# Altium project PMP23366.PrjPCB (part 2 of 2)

## Sheet PMP23366_RevB_SH3.SchDoc: Power Monitor and Source Selection
size 431 x 279 mm; Date: Not shown in title block; ApprovedBy: Not shown in title block; CheckedBy: Not shown in title block; Author: Not shown in title block; CompanyName: Not shown in title block; DrawnBy: D Strasser; Engineer: Not shown in title block; Organization: Not shown in title block; Address1: Not shown in title block; Address2: Not shown in title block; Address3: Not shown in title block; Address4: Not shown in title block; DocumentNumber: 3; Revision: Use project parameter SCH_Rev; SheetNumber: 3; SheetTotal: 4; PageSetup: Record=PageOptions¦CenterHorizontal=True¦CenterVertical=True¦PrintScale=1.00¦XCorrection=1.00¦YCorrection=1.00¦PrintKind=0¦BorderSize=5000000¦LeftOffset=0¦BottomOffset=0¦Orientation=2¦PaperLength=1000¦PaperWidth=1000¦Scale=100¦PaperSource=15¦PrintQuality=600¦MediaType=1¦DitherType=10¦PaperKind=Letter¦PrintScaleMode=1
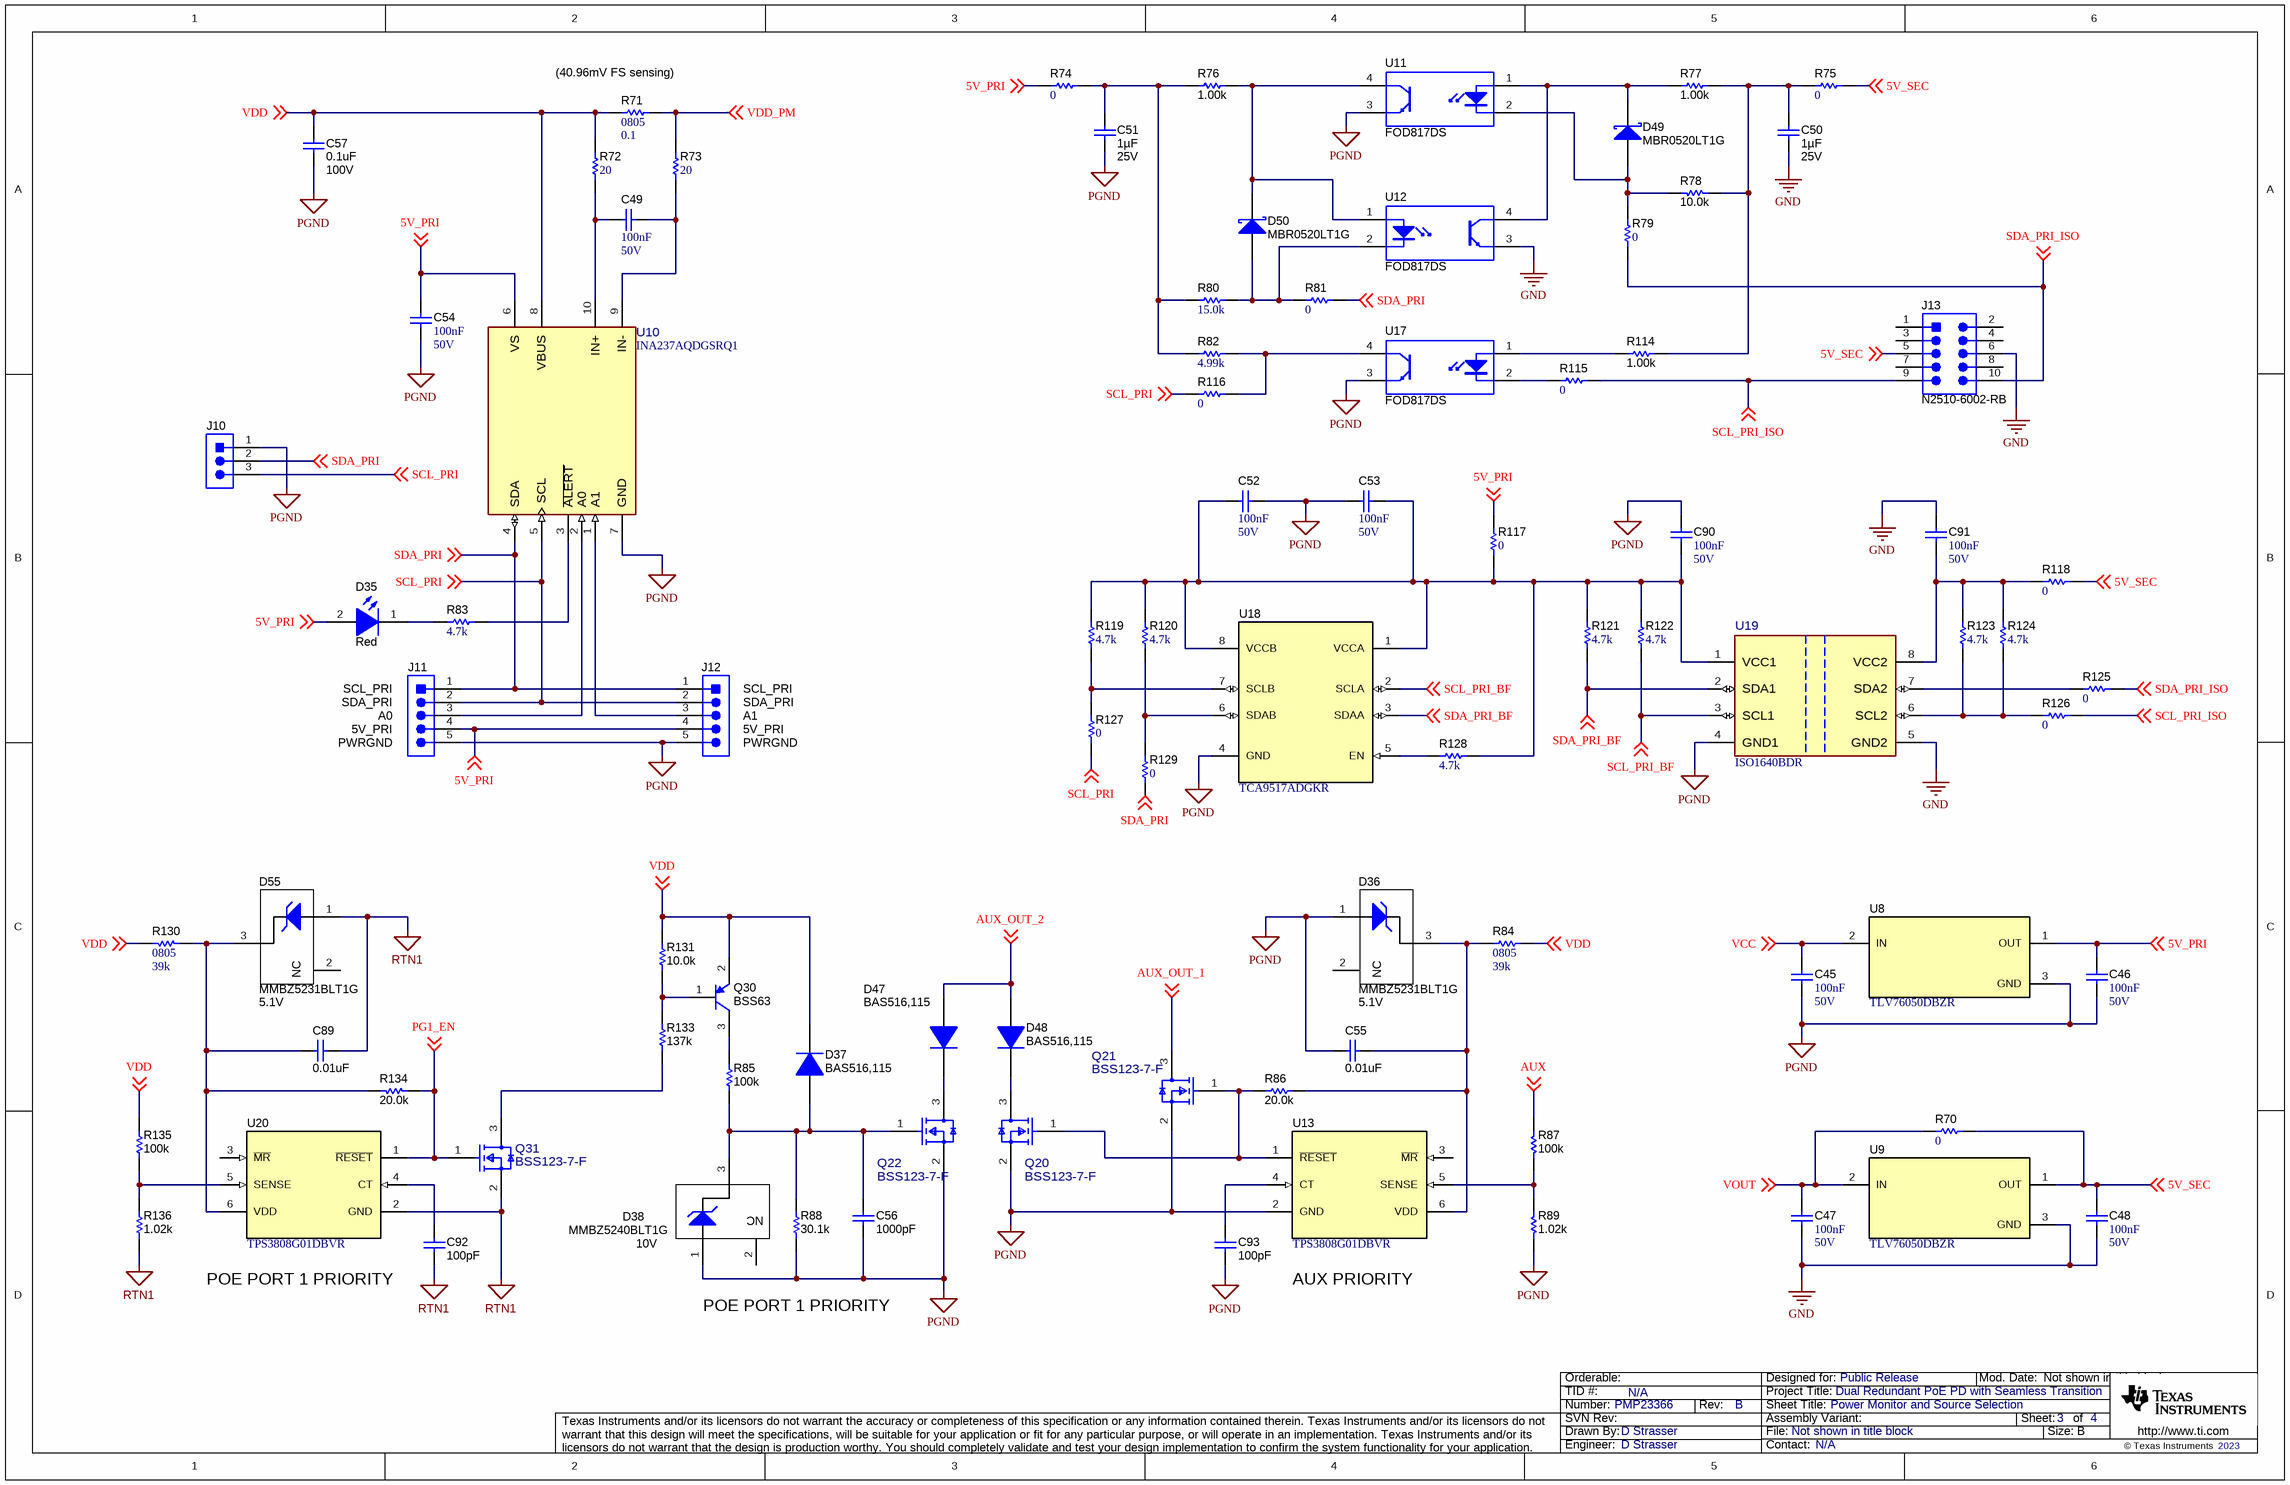
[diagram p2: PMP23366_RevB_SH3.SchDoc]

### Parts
C45  Cap_F: 100nF  VDC_V: 50V  [0603L]  (hidden comment: 885012206095)
C46  Cap_F: 100nF  VDC_V: 50V  [0603L]  (hidden comment: 885012206095)
C47  Cap_F: 100nF  VDC_V: 50V  [0603L]  (hidden comment: 885012206095)
C48  Cap_F: 100nF  VDC_V: 50V  [0603L]  (hidden comment: 885012206095)
C49  Cap_F: 100nF  VDC_V: 50V  [0603L]  (hidden comment: 885012206095)
C50  Cap_F: 1µF  VDC_V: 25V  [0805_HV1]  (hidden comment: TMK212B7105KG-T)
C51  Cap_F: 1µF  VDC_V: 25V  [0805_HV1]  (hidden comment: TMK212B7105KG-T)
C52  Cap_F: 100nF  VDC_V: 50V  [0603L]  (hidden comment: 885012206095)
C53  Cap_F: 100nF  VDC_V: 50V  [0603L]  (hidden comment: 885012206095)
C54  Cap_F: 100nF  VDC_V: 50V  [0603L]  (hidden comment: 885012206095)
C55  ValueDisplayed: 0.01uF  [0603L]  (hidden comment: Capacitor)
C56  ValueDisplayed: 1000pF  [0603L]  (hidden comment: Capacitor)
C57  ValueDisplayed: 0.1uF  Value2: 100V  [0805_HV]  (hidden comment: Capacitor)
C89  ValueDisplayed: 0.01uF  [0603L]  (hidden comment: Capacitor)
C90  Cap_F: 100nF  VDC_V: 50V  [0603L]  (hidden comment: 885012206095)
C91  Cap_F: 100nF  VDC_V: 50V  [0603L]  (hidden comment: 885012206095)
C92  ValueDisplayed: 100pF  [0603L]  (hidden comment: 885012006057)
C93  ValueDisplayed: 100pF  [0603L]  (hidden comment: 885012006057)
D35  value Red  [HLMP-Q150_Red]  (hidden comment: HLMP-Q150-F0011)
D36  MMBZ5231BLT1G  value 5.1V  [SOT-23L]
D37  BAS516,115  [SOD-523]
D38  MMBZ5240BLT1G  value 10V  [SOT-23L]
D47  BAS516,115  [SOD-523]
D48  BAS516,115  [SOD-523]
D49  MBR0520LT1G  [SOD-123]
D50  MBR0520LT1G  [SOD-123]
D55  MMBZ5231BLT1G  value 5.1V  [SOT-23L]
J10  TSW-103-08-G-S  [Samtec_TSW-103-08-x-S]  (value not drawn)
J11  HTSW-105-07-G-S  [Samtec_HTSW-105-07-G-S]  (value not drawn)
J12  HTSW-105-07-G-S  [Samtec_HTSW-105-07-G-S]  (value not drawn)
J13  N2510-6002-RB  [CONN_2510-6002]
Q20  BSS123-7-F  [FP-BSS123-7-F_SOT23-MFG]
Q21  BSS123-7-F  [FP-BSS123-7-F_SOT23-MFG]
Q22  BSS123-7-F  [FP-BSS123-7-F_SOT23-MFG]
Q30  BSS63  [SOT-23L]
Q31  BSS123-7-F  [FP-BSS123-7-F_SOT23-MFG]
R70  ValueDisplayed: 0  [0603L]  (hidden comment: CRCW06030000Z0EA)
R71  PackageReference: 0805  ValueDisplayed: 0.1  [0805_HV1]  (hidden comment: RL0805FR-070R025L)
R72  ValueDisplayed: 20  [0603L]  (hidden comment: CRCW060320R0JNEA)
R73  ValueDisplayed: 20  [0603L]  (hidden comment: CRCW060320R0JNEA)
R74  ValueDisplayed: 0  [0603L]  (hidden comment: CRCW06030000Z0EA)
R75  ValueDisplayed: 0  [0603L]  (hidden comment: CRCW06030000Z0EA)
R76  value 1.00k  [0603L]  (hidden comment: Resistor)
R77  value 1.00k  [0603L]  (hidden comment: Resistor)
R78  ValueDisplayed: 10.0k  [0603L]  (hidden comment: Resistor)
R79  ValueDisplayed: 0  [0603L]  (hidden comment: CRCW06030000Z0EA)
R80  ValueDisplayed: 15.0k  [0603L]  (hidden comment: CRCW060315K0FKEA)
R81  ValueDisplayed: 0  [0603L]  (hidden comment: CRCW06030000Z0EA)
R82  ValueDisplayed: 4.99k  [0603L]  (hidden comment: CRCW06034K99FKEA)
R83  ValueDisplayed: 4.7k  [0603L]  (hidden comment: CRCW06034K70JNEA)
R84  PackageReference: 0805  ValueDisplayed: 39k  [0805_HV1]  (hidden comment: CRCW080539K0JNEA)
R85  ValueDisplayed: 100k  [0603L]  (hidden comment: Resistor)
R86  ValueDisplayed: 20.0k  [0603L]  (hidden comment: Resistor)
R87  ValueDisplayed: 100k  [0603L]  (hidden comment: Resistor)
R88  ValueDisplayed: 30.1k  [0603L]  (hidden comment: Resistor)
R89  ValueDisplayed: 1.02k  [0603L]  (hidden comment: Resistor)
R114  value 1.00k  [0603L]  (hidden comment: Resistor)
R115  ValueDisplayed: 0  [0603L]  (hidden comment: CRCW06030000Z0EA)
R116  ValueDisplayed: 0  [0603L]  (hidden comment: CRCW06030000Z0EA)
R117  ValueDisplayed: 0  [0603L]  (hidden comment: CRCW06030000Z0EA)
R118  ValueDisplayed: 0  [0603L]  (hidden comment: CRCW06030000Z0EA)
R119  ValueDisplayed: 4.7k  [0603L]  (hidden comment: CRCW06034K70JNEA)
R120  ValueDisplayed: 4.7k  [0603L]  (hidden comment: CRCW06034K70JNEA)
R121  ValueDisplayed: 4.7k  [0603L]  (hidden comment: CRCW06034K70JNEA)
R122  ValueDisplayed: 4.7k  [0603L]  (hidden comment: CRCW06034K70JNEA)
R123  ValueDisplayed: 4.7k  [0603L]  (hidden comment: CRCW06034K70JNEA)
R124  ValueDisplayed: 4.7k  [0603L]  (hidden comment: CRCW06034K70JNEA)
R125  ValueDisplayed: 0  [0603L]  (hidden comment: CRCW06030000Z0EA)
R126  ValueDisplayed: 0  [0603L]  (hidden comment: CRCW06030000Z0EA)
R127  ValueDisplayed: 0  [0603L]  (hidden comment: CRCW06030000Z0EA)
R128  ValueDisplayed: 4.7k  [0603L]  (hidden comment: CRCW06034K70JNEA)
R129  ValueDisplayed: 0  [0603L]  (hidden comment: CRCW06030000Z0EA)
R130  PackageReference: 0805  ValueDisplayed: 39k  [0805_HV1]  (hidden comment: CRCW080539K0JNEA)
R131  ValueDisplayed: 10.0k  [0603L]  (hidden comment: Resistor)
R133  ValueDisplayed: 137k  [0603L]  (hidden comment: Resistor)
R134  ValueDisplayed: 20.0k  [0603L]  (hidden comment: Resistor)
R135  ValueDisplayed: 100k  [0603L]  (hidden comment: Resistor)
R136  ValueDisplayed: 1.02k  [0603L]  (hidden comment: Resistor)
U8  TLV76050DBZR  [DBZ0003A_N]
U9  TLV76050DBZR  [DBZ0003A_N]
U10  INA237AQDGSRQ1  [DGS0010A-MFG]
U11  FOD817DS  [N04C]
U12  FOD817DS  [N04C]
U13  TPS3808G01DBVR  [DBV0006A_N]
U17  FOD817DS  [N04C]
U18  TCA9517ADGKR  [DGK0008A_N]
U19  ISO1640BDR  [D0008A-MFG]
U20  TPS3808G01DBVR  [DBV0006A_N]

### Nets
GND: C47.2 C48.2 C50.1 C91.1 J13.6 U9.3(GND) U12.3(E) U19.5(GND2)
PGND: C45.2 C46.2 C51.1 C52.1 C53.2 C54.2 C55.1 C56.2 C57.1 C90.1 C93.2 D36.1(A) D38.1(A) J10.1 J11.5 J12.5 Q20.2(S) Q21.2(S) Q22.2(S) R88.1 R89.1 U8.3(GND) U10.7(GND) U11.3(E) U13.2(GND) U17.3(E) U18.4(GND) U19.4(GND1)
RTN1: C89.1 C92.2 D55.1(A) Q31.2(S) R136.1 U20.2(GND)
5V_PRI: C46.1 C54.1 D35.2(A) J11.4 J12.4 R74.1 R117.2 U8.1(OUT) U10.6(VS) ; off-sheet 5V_PRI
5V_SEC: C48.1 J13.5 R70.2 R75.1 R118.2 U9.1(OUT) ; off-sheet 5V_SEC
AUX: R87.2 ; off-sheet AUX
AUX_OUT_1: Q21.3(D) ; off-sheet AUX_OUT_1
AUX_OUT_2: D47.2(A) D48.2(A) ; off-sheet AUX_OUT_2
PG1_EN: Q31.1(G) R134.2 U20.1(~{RESET}) ; off-sheet PG1_EN
SCL_PRI: J10.3 J11.2 J12.2 R116.2 R127.1 U10.5(SCL) ; off-sheet SCL_PRI
SCL_PRI_BF: R122.1 U18.2(SCLA) U19.3(SCL1) ; off-sheet SCL_PRI_BF
SCL_PRI_ISO: J13.9 R115.2 R126.2 ; off-sheet SCL_PRI_ISO
SDA_PRI: J10.2 J11.1 J12.1 R81.2 R129.1 U10.4(SDA) ; off-sheet SDA_PRI
SDA_PRI_BF: R121.1 U18.3(SDAA) U19.2(SDA1) ; off-sheet SDA_PRI_BF
SDA_PRI_ISO: J13.10 R79.2 R125.2 ; off-sheet SDA_PRI_ISO
VCC: C45.1 U8.2(IN) ; off-sheet VCC
VDD: C57.2 D37.1(K) Q30.2(E) R71.1 R72.1 R84.1 R130.1 R131.2 R135.2 U10.8(VBUS) ; off-sheet VDD
VDD_PM: R71.2 R73.1 ; off-sheet VDD_PM
VOUT: C47.1 R70.1 U9.2(IN) ; off-sheet VOUT
NetC49_1: C49.1 R73.2 U10.9(IN-)
NetC49_2: C49.2 R72.2 U10.10(IN+)
NetC50_2: C50.2 R75.2 R77.2 R78.2 R114.2
NetC51_2: C51.2 R74.2 R76.1 R80.1 R82.1
NetC52_2: C52.2 C53.1 C90.2 R117.1 R119.1 R120.2 R121.2 R122.2 R128.1 U18.1(VCCA) U18.8(VCCB) U19.1(VCC1)
NetC55_2: C55.2 D36.3(K) R84.2 R86.1 U13.6(VDD)
NetC56_1: C56.1 D37.2(A) D38.3(K) Q22.1(G) R85.1 R88.2
NetC89_2: C89.2 D55.3(K) R130.2 R134.1 U20.6(VDD)
NetC91_2: C91.2 R118.1 R123.2 R124.2 U19.8(VCC2)
NetC92_1: C92.1 U20.4(CT)
NetC93_1: C93.1 U13.4(CT)
NetD35_1: D35.1(K) R83.1
NetD47_1: D47.1(K) Q22.3(D)
NetD48_1: D48.1(K) Q20.3(D)
NetD49_1: D49.1(K) R77.1 U11.1(A) U12.4(C)
NetD49_2: D49.2(A) R78.1 R79.1 U11.2(K)
NetD50_1: D50.1(K) R76.2 U11.4(C) U12.1(A)
NetD50_2: D50.2(A) R80.2 R81.1 U12.2(K)
NetJ11_3: J11.3 U10.2(A0)
NetJ12_3: J12.3 U10.1(A1)
NetQ20_1: Q20.1(G) Q21.1(G) R86.2 U13.1(~{RESET})
NetQ30_1: Q30.1(B) R131.1 R133.1
NetQ30_3: Q30.3(C) R85.2
NetQ31_3: Q31.3(D) R133.2
NetR82_2: R82.2 R116.1 U17.4(C)
NetR83_2: R83.2 U10.3(~{ALERT})
NetR87_1: R87.1 R89.2 U13.5(SENSE)
NetR114_1: R114.1 U17.1(A)
NetR115_1: R115.1 U17.2(K)
NetR119_2: R119.2 R127.2 U18.7(SCLB)
NetR120_1: R120.1 R129.2 U18.6(SDAB)
NetR123_1: R123.1 R124.1 R126.1 U19.6(SCL2)
NetR125_1: R125.1 U19.7(SDA2)
NetR128_2: R128.2 U18.5(EN)
NetR135_1: R135.1 R136.2 U20.5(SENSE)

Not connected (* = marked no-connect by the designer): D36 2(NC); D38 2(NC); D55 2(NC); J13 1 2 3 4 7 8; U13 3(~{MR}); U20 3(~{MR})

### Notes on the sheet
- (near R71) (40.96mV FS sensing)
- (near J11) SDA_PRI
- SCL_PRI
- (near J12) SCL_PRI
- (near J12) SDA_PRI
- (near J11) A0
- (near J11) 5V_PRI
- (near J11) PWRGND
- (near J12) A1
- (near J12) 5V_PRI
- (near J12) PWRGND
- POE PORT 1 PRIORITY
- AUX PRIORITY

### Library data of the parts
C45-C49 C52-C54 C90 C91 = CMP-0006837-4: CAP, CERM, 0.1 uF, 50 V, +/- 10%, X7R, 0603; Manufacturer: Wurth Elektronik; TaMin_C: -55°C; Polarized: N; SizeAreaWB_mm2: 4.68; Value1: Unknown; U/M: EA; Value: 0.1uF; TaMax_C: 125°C; SizeZ_mm: 1; SizeX_mm: 1.6; SizeY_mm: 0.8; Cap_Case: 0603; SizeArea_mm2: 1.28; AEC Category: Q200
C50 C51 = CMP-0008412-2: CAP, CERM, 1 uF, 25 V, +/- 10%, X7R, 0805; Manufacturer: Taiyo Yuden; TaMin_C: -55°C; Polarized: N; SizeAreaWB_mm2: 6.75; Value1: Unknown; U/M: EA; Value: 1uF; TaMax_C: 125°C; SizeZ_mm: 1.45; SizeX_mm: 2; SizeY_mm: 1.25; Cap_Case: 0805; SizeArea_mm2: 2.5; AEC Category: Q200
C55 C89 = CMP-0007043-4: CAP, CERM, 0.01 uF, 50 V, +/- 10%, X7R, 0603; PartNumber: C1608X7R1H103K080AA; Manufacturer: TDK; Polarized: N; Value: 0.01uF; U/M: EA; Cap_F: 10nF; ESR_ohm: 0.0539; Value1: 0.0539 ohm; VDC_V: 50V; TaMin_C: -55°C; TaMax_C: 125°C; Cap_Case: 0603; SizeArea_mm2: 1.28; SizeAreaWB_mm2: 4.68; SizeX_mm: 1.6; SizeY_mm: 0.8; SizeZ_mm: 1; AEC Category: Q200
C56 = CMP-0007432-5: CAP, CERM, 1000 pF, 50 V, +/- 10%, X7R, 0603; PartNumber: GRM188R71H102KA01D; Manufacturer: MuRata; Polarized: N; Value: 1000pF; U/M: EA; Cap_F: 1nF; Value1: Unknown; VDC_V: 50V; TaMin_C: -55°C; TaMax_C: 125°C; Cap_Case: 0603; SizeArea_mm2: 1.28; SizeAreaWB_mm2: 4.68; SizeX_mm: 1.6; SizeY_mm: 0.8; SizeZ_mm: 1; AEC Category: Q200
C57 = CMP-0007886-2: CAP, CERM, 0.1 uF, 100 V, +/- 10%, X7R, 0805; PartNumber: C2012X7R2A104K125AA; Manufacturer: TDK; Polarized: N; Value: 0.1uF; U/M: EA; Cap_F: 100nF; ESR_ohm: 0.020726; Value1: 0.020726 ohm; IRMS_A: 1.456A; TaMin_C: -55°C; TaMax_C: 125°C; Cap_Case: 0805; SizeArea_mm2: 2.5; SizeAreaWB_mm2: 6.75; SizeX_mm: 2; SizeY_mm: 1.25; SizeZ_mm: 1.45; AEC Category: Q200
C92 C93 = CMP-0006822-4: CAP, CERM, 100 pF, 50 V, +/- 5%, C0G/NP0, 0603; Manufacturer: Wurth Elektronik; TaMin_C: -55°C; Polarized: N; SizeAreaWB_mm2: 4.68; Value1: Unknown; U/M: EA; Value: 100pF; TaMax_C: 125°C; SizeZ_mm: 1; SizeX_mm: 1.6; SizeY_mm: 0.8; Cap_Case: 0603; Value2: 50V; SizeArea_mm2: 1.28; AEC Category: Q200
D35 = CMP-0002939-3: LED, Red, SMD; Manufacturer: Avago; Vf_V: 1.6V; Ir_A: 10µA; Value1: W; Vr_V: 15V; Io_A: 1mA; Angle: 90; Tjmax_C: 100°C
D36 D55 = CMP-0005999-3: Diode, Zener, 5.1 V, 225 mW, SOT-23; Manufacturer: ON Semiconductor; SizeZ_mm: 1.1; SizeAreaWB_mm2: 14; Power_W: 225mW; SizeY_mm: 3; SizeArea_mm2: 7.5; RJA_CperW: 556; SizeX_mm: 2.5; AEC Category: Q101; Value1: 0.225W
D37 D47 D48 = CMP-0076979-3: Diode, Switching, 100 V, 0.25 A, SOD-523; Manufacturer: Nexperia; Value: 100V; SizeAreaWB_mm2: 5.13; Vf_V: 1.25V; SizeArea_mm2: 1.53; SizeY_mm: 0.9; Green_Lifecycle: Not Set; AEC Category: Q101; SizeX_mm: 1.7; Green_REACh: Incomplete; Io_A: 250mA; TJmax_C: 150°C; SizeZ_mm: 0.65; Value1: 0.25A
D38 = CMP-0005949-3: Diode, Zener, 10 V, 225 mW, SOT-23; Manufacturer: ON Semiconductor; SizeAreaWB_mm2: 14; RJA_CperW: 556; SizeArea_mm2: 7.5; SizeY_mm: 3; Value1: 0.225W; SizeZ_mm: 1.1; AEC Category: Q101; SizeX_mm: 2.5; Power_W: 225mW
D49 D50 = CMP-0028524-2: Diode, Schottky, 20 V, 0.5 A, SOD-123; Manufacturer: ON Semiconductor; Green_REACh: Passed; TJmax_C: 125°C; Value1: 0.5A; SizeZ_mm: 1.35; Value2: 0.385V; Vf_V: 385mV; AEC Category: Q101; SizeY_mm: 1.7; Value: 20V; Io_A: 500mA; SizeX_mm: 3.85; Green_Lifecycle: Active; RJC_CperW: 150; SizeAreaWB_mm2: 13.095; SizeArea_mm2: 6.545
J10 = CMP-0079327-1: Header, 2.54mm, 3x1, Gold, TH; Manufacturer: Samtec; Pitch_mm: 2.54; Gender: Male; Cert_UL: Y; Shrouded: N; Row_Count: 1
J11 J12 = CMP-0075485-1: Header, 100mil, 5x1, Gold, TH; Manufacturer: Samtec; Green_REACh: Passed; CT: False; Green_Lifecycle: Active; CNHeader: True
J13 = CMP-0055448-2: Header (shrouded), 100mil, 5x2, High-Temperature, Gold, TH; Manufacturer: 3M; Green_Lifecycle: Active; Green_REACh: Passed
Q20-Q22 Q31 = CMP-0087176-1: MOSFET N-CH 100V 170MA SOT23-3; Manufacturer: Diodes Incorporated; Vgs_V: 20V; ChMode: False; AEC Qualified: No; SizeZ_mm: 1.1mm; Rdson45_ohm: 6
Q30 = CMP-0000366-2: Transistor, PNP, 100 V, 0.2 A, SOT-23; Manufacturer: Fairchild Semiconductor; TaMax_C: 150°C; Value1: 0.2 A; Vcesat1_V: 250mV; SizeX_mm: 2.5; SizeY_mm: 3; TaMin_C: -55°C; IcRated_A: 200mA; CompType: BJT; SizeZ_mm: 1.1; AEC Qualified: N; Value: 100 V; SizeArea_mm2: 7.5; NPN: 0; Vceo_V: 100V; PNP: 1; AEC Category: Q101; SizeAreaWB_mm2: 14; U/M: EA
R70 R74 R75 R79 R81 R115-R118 R125-R127 R129 = CMP-0025697-4: RES, 0, 5%, 0.1 W, AEC-Q200 Grade 0, 0603; Manufacturer: Vishay-Dale; Power_W: 100mW; TempCo: 200 ppm/C; Value_Code: 0000; Value: 0; EIA_Code: E24; SizeX_mm: 1.6; SizeY_mm: 0.8; SizeZ_mm: 1; Value2: 0.1W; SizeArea_mm2: 1.28; AEC Qualified: Y; VDC_V: 75V; AEC Category: Q200
R71 = CMP-0080609-1: RES, 0.025, 1%, 0.125 W, AEC-Q200 Grade 1, 0805; Manufacturer: Yageo America; Power_W: 125mW; TempCo: 600 ppm/C; SizeAreaWB_mm2: 6.75; Value_Code: R100; Value: 0.1; EIA_Code: E96; Res_ohm: 0.025; SizeX_mm: 2; SizeY_mm: 1.25; SizeZ_mm: 1.45; Value2: 0.125W; SizeArea_mm2: 2.5; AEC Qualified: Y; AEC Grade: 1; AEC Category: Q200
R72 R73 = CMP-0025754-4: RES, 20, 5%, 0.1 W, AEC-Q200 Grade 0, 0603; Manufacturer: Vishay-Dale; Power_W: 100mW; TempCo: 200 ppm/C; Value_Code: 20R0; Value: 20; EIA_Code: E24; SizeX_mm: 1.6; SizeY_mm: 0.8; SizeZ_mm: 1; Value2: 0.1W; SizeArea_mm2: 1.28; AEC Qualified: Y; VDC_V: 75V; AEC Category: Q200; AEC Grade: 0
R76 R77 R114 = CMP-0022109-5: RES, 1.00 k, 1%, 0.1 W, AEC-Q200 Grade 0, 0603; PartNumber: CRCW06031K00FKEA; Manufacturer: Vishay-Dale; Res_ohm: 1k; Value_Code: 1k00; Power_W: 100mW; Value2: 0.1W; VDC_V: 75V; TempCo: 100 ppm/C; EIA_Code: E96; AEC Category: Q200; AEC Grade: 0; AEC Qualified: Y; SizeArea_mm2: 1.28; SizeX_mm: 1.6; SizeY_mm: 0.8; SizeZ_mm: 1
R78 R131 = CMP-0021998-4: RES, 10.0 k, 1%, 0.1 W, AEC-Q200 Grade 0, 0603; PartNumber: CRCW060310K0FKEA; Manufacturer: Vishay-Dale; Value: 10.0k; Res_ohm: 10k; Value_Code: 10k0; Power_W: 100mW; Value2: 0.1W; VDC_V: 75V; TempCo: 100 ppm/C; SizeArea_mm2: 1.28; SizeX_mm: 1.6; SizeY_mm: 0.8; SizeZ_mm: 1; EIA_Code: E96; AEC Category: Q200; AEC Qualified: Y; AEC Grade: 0
R80 = CMP-0022066-4: RES, 15.0 k, 1%, 0.1 W, AEC-Q200 Grade 0, 0603; Manufacturer: Vishay-Dale; Power_W: 100mW; TempCo: 100 ppm/C; Value_Code: 15k0; Value: 15.0k; EIA_Code: E96; Res_ohm: 15k; SizeX_mm: 1.6; SizeY_mm: 0.8; SizeZ_mm: 1; Value2: 0.1W; SizeArea_mm2: 1.28; AEC Qualified: Y; VDC_V: 75V; AEC Category: Q200; AEC Grade: 0
R82 = CMP-0022458-4: RES, 4.99 k, 1%, 0.1 W, AEC-Q200 Grade 0, 0603; Manufacturer: Vishay-Dale; Power_W: 100mW; TempCo: 100 ppm/C; Value_Code: 4k99; Value: 4.99k; EIA_Code: E96; SizeX_mm: 1.6; SizeY_mm: 0.8; SizeZ_mm: 1; Value2: 0.1W; SizeArea_mm2: 1.28; AEC Qualified: Y; VDC_V: 75V; AEC Category: Q200; AEC Grade: 0
R83 R119-R124 R128 = CMP-0025817-4: RES, 4.7 k, 5%, 0.1 W, AEC-Q200 Grade 0, 0603; Manufacturer: Vishay-Dale; Power_W: 100mW; TempCo: 200 ppm/C; Value_Code: 4k70; Value: 4.7k; EIA_Code: E24; SizeX_mm: 1.6; SizeY_mm: 0.8; SizeZ_mm: 1; Value2: 0.1W; SizeArea_mm2: 1.28; AEC Qualified: Y; VDC_V: 75V; AEC Category: Q200; AEC Grade: 0
R84 R130 = CMP-0020536-3: RES, 39 k, 5%, 0.125 W, AEC-Q200 Grade 0, 0805; Manufacturer: Vishay-Dale; Power_W: 125mW; TempCo: 200 ppm/C; Value_Code: 39k0; Value: 39k; EIA_Code: E24; SizeX_mm: 2; SizeY_mm: 1.25; SizeZ_mm: 1.45; Value2: 0.125W; SizeArea_mm2: 2.5; AEC Qualified: Y; VDC_V: 150V; AEC Category: Q200; AEC Grade: 0
R85 R87 R135 = CMP-0021990-4: RES, 100 k, 1%, 0.1 W, AEC-Q200 Grade 0, 0603; PartNumber: CRCW0603100KFKEA; Manufacturer: Vishay-Dale; Value: 100k; Power_W: 100mW; Value2: 0.1W; VDC_V: 75V; TempCo: 100 ppm/C; SizeArea_mm2: 1.28; SizeX_mm: 1.6; SizeY_mm: 0.8; SizeZ_mm: 1; EIA_Code: E96; AEC Category: Q200; AEC Qualified: Y; AEC Grade: 0
R86 R134 = CMP-0022204-4: RES, 20.0 k, 1%, 0.1 W, AEC-Q200 Grade 0, 0603; PartNumber: CRCW060320K0FKEA; Manufacturer: Vishay-Dale; Value: 20.0k; Res_ohm: 20k; Value_Code: 20k0; Power_W: 100mW; Value2: 0.1W; VDC_V: 75V; TempCo: 100 ppm/C; EIA_Code: E96; SizeArea_mm2: 1.28; SizeX_mm: 1.6; SizeY_mm: 0.8; SizeZ_mm: 1; AEC Category: Q200; AEC Qualified: Y; AEC Grade: 0
R88 = CMP-0022324-4: RES, 30.1 k, 1%, 0.1 W, AEC-Q200 Grade 0, 0603; PartNumber: CRCW060330K1FKEA; Manufacturer: Vishay-Dale; Value: 30.1k; Value_Code: 30k1; Power_W: 100mW; Value2: 0.1W; VDC_V: 75V; TempCo: 100 ppm/C; SizeArea_mm2: 1.28; SizeX_mm: 1.6; SizeY_mm: 0.8; SizeZ_mm: 1; EIA_Code: E96; AEC Category: Q200; AEC Qualified: Y; AEC Grade: 0
R89 R136 = CMP-0022110-4: RES, 1.02 k, 1%, 0.1 W, AEC-Q200 Grade 0, 0603; PartNumber: CRCW06031K02FKEA; Manufacturer: Vishay-Dale; Value: 1.02k; Value_Code: 1k02; Power_W: 100mW; Value2: 0.1W; VDC_V: 75V; TempCo: 100 ppm/C; SizeArea_mm2: 1.28; SizeX_mm: 1.6; SizeY_mm: 0.8; SizeZ_mm: 1; EIA_Code: E96; AEC Category: Q200; AEC Qualified: Y; AEC Grade: 0
R133 = CMP-0022040-4: RES, 137 k, 1%, 0.1 W, AEC-Q200 Grade 0, 0603; PartNumber: CRCW0603137KFKEA; Manufacturer: Vishay-Dale; Value: 137k; Power_W: 100mW; Value2: 0.1W; VDC_V: 75V; TempCo: 100 ppm/C; SizeArea_mm2: 1.28; SizeX_mm: 1.6; SizeY_mm: 0.8; SizeZ_mm: 1; EIA_Code: E96; AEC Category: Q200; AEC Qualified: Y; AEC Grade: 0
U8 U9 = CMP-0074892-1: 100-mA, 30-V, Fixed-Output, Linear-Voltage Regulator, DBZ0003A (SOT-23-3); Alternate PartNumber: TLV76050DBZT; Alternate Manufacturer: Texas Instruments; SizeAreaWB_mm2: 14.0; SizeZ_mm: 1.12; SizeX_mm: 2.5; SizeY_mm: 3.0; SizeArea_mm2: 7.5; CompType: IC; AEC Qualified: N; AEC Category: Q200
U10 = CMP-0088571-2: High-Voltage, Zero-Drift, 16-Bit ADC, I 2C, Bidirectional Shunt Current, Bus Voltage, Power, and Temperature Monitor; Manufacturer: Texas Instruments; Number Of Converters: 1; AEC Category: Q200; CompType: IC; Standoff Height: 0.05mm; Interface: I2C; Data Polarity: Differential; SizeZ_mm: 1.1mm
U11 U12 U17 = CMP-0006165-3: Optocoupler, 5 kV, 300-600% CTR, SMT; Manufacturer: Fairchild Semiconductor; CTR (Max): 600%; CTR (Min): 300%; Voltage_Isolation_Vrms: 5kV
U13 U20 = CMP-0032355-1: Low Quiescent Current, Programmable-Delay Supervisory Circuit, 1 Supply Monitored, -40 to 125 degC, 6-pin SOT-23 (DBV), Green (RoHS & no Sb/Br); Manufacturer: Texas Instruments; # of Supplies Monitored: 1; Iq(Typ)(uA): 2.4; Output Driver Type / Reset Output: Active-low, Open-drain; Rating: Catalog; SubFamily: Supervisor and Reset IC; Threshold Voltage 1 (typ)(Typ)(V): Adjustable; VCC(Max)(V): 6.5; VCC(Min)(V): 1.7
U18 = CMP-0065788-2: Level-Translating I2C Bus Repeater, DGK0008A (VSSOP-8); Alternate Manufacturer: Texas Instruments; SizeAreaWB_mm2: 23.6; SizeZ_mm: 1.1; SizeX_mm: 4.9; SizeY_mm: 3; SizeArea_mm2: 14.7; CompType: IC; AEC Category: Q200; AEC Qualified: N
U19 = CMP-0091761-1: Manufacturer: Texas Instruments; TaMin_C: -40°C; AEC Qualified: No; Standoff Height: 0.11mm; Min Supply Voltage: 2.25V; SizeZ_mm: 1.75mm; Nominal Supply Current: 2.7-5.3mA; Interface: I2C; TaMax_C: +125°C; TJmax_C: +150°C; Max Supply Voltage: 5.5V

## Sheet PMP23366_RevB_SH4.SchDoc: Active Clamp Forward Converter
size 431 x 279 mm; Date: Not shown in title block; ApprovedBy: Not shown in title block; CheckedBy: Not shown in title block; Author: Not shown in title block; CompanyName: Not shown in title block; DrawnBy: D Strasser; Engineer: Not shown in title block; Organization: Not shown in title block; Address1: Not shown in title block; Address2: Not shown in title block; Address3: Not shown in title block; Address4: Not shown in title block; DocumentNumber: 4; Revision: Use project parameter SCH_Rev; SheetNumber: 4; SheetTotal: 4; PageSetup: Record=PageOptions¦CenterHorizontal=True¦CenterVertical=True¦PrintScale=1.00¦XCorrection=1.00¦YCorrection=1.00¦PrintKind=0¦BorderSize=5000000¦LeftOffset=0¦BottomOffset=0¦Orientation=2¦PaperLength=1000¦PaperWidth=1000¦Scale=100¦PaperSource=15¦PrintQuality=600¦MediaType=1¦DitherType=10¦PaperKind=Letter¦PrintScaleMode=1
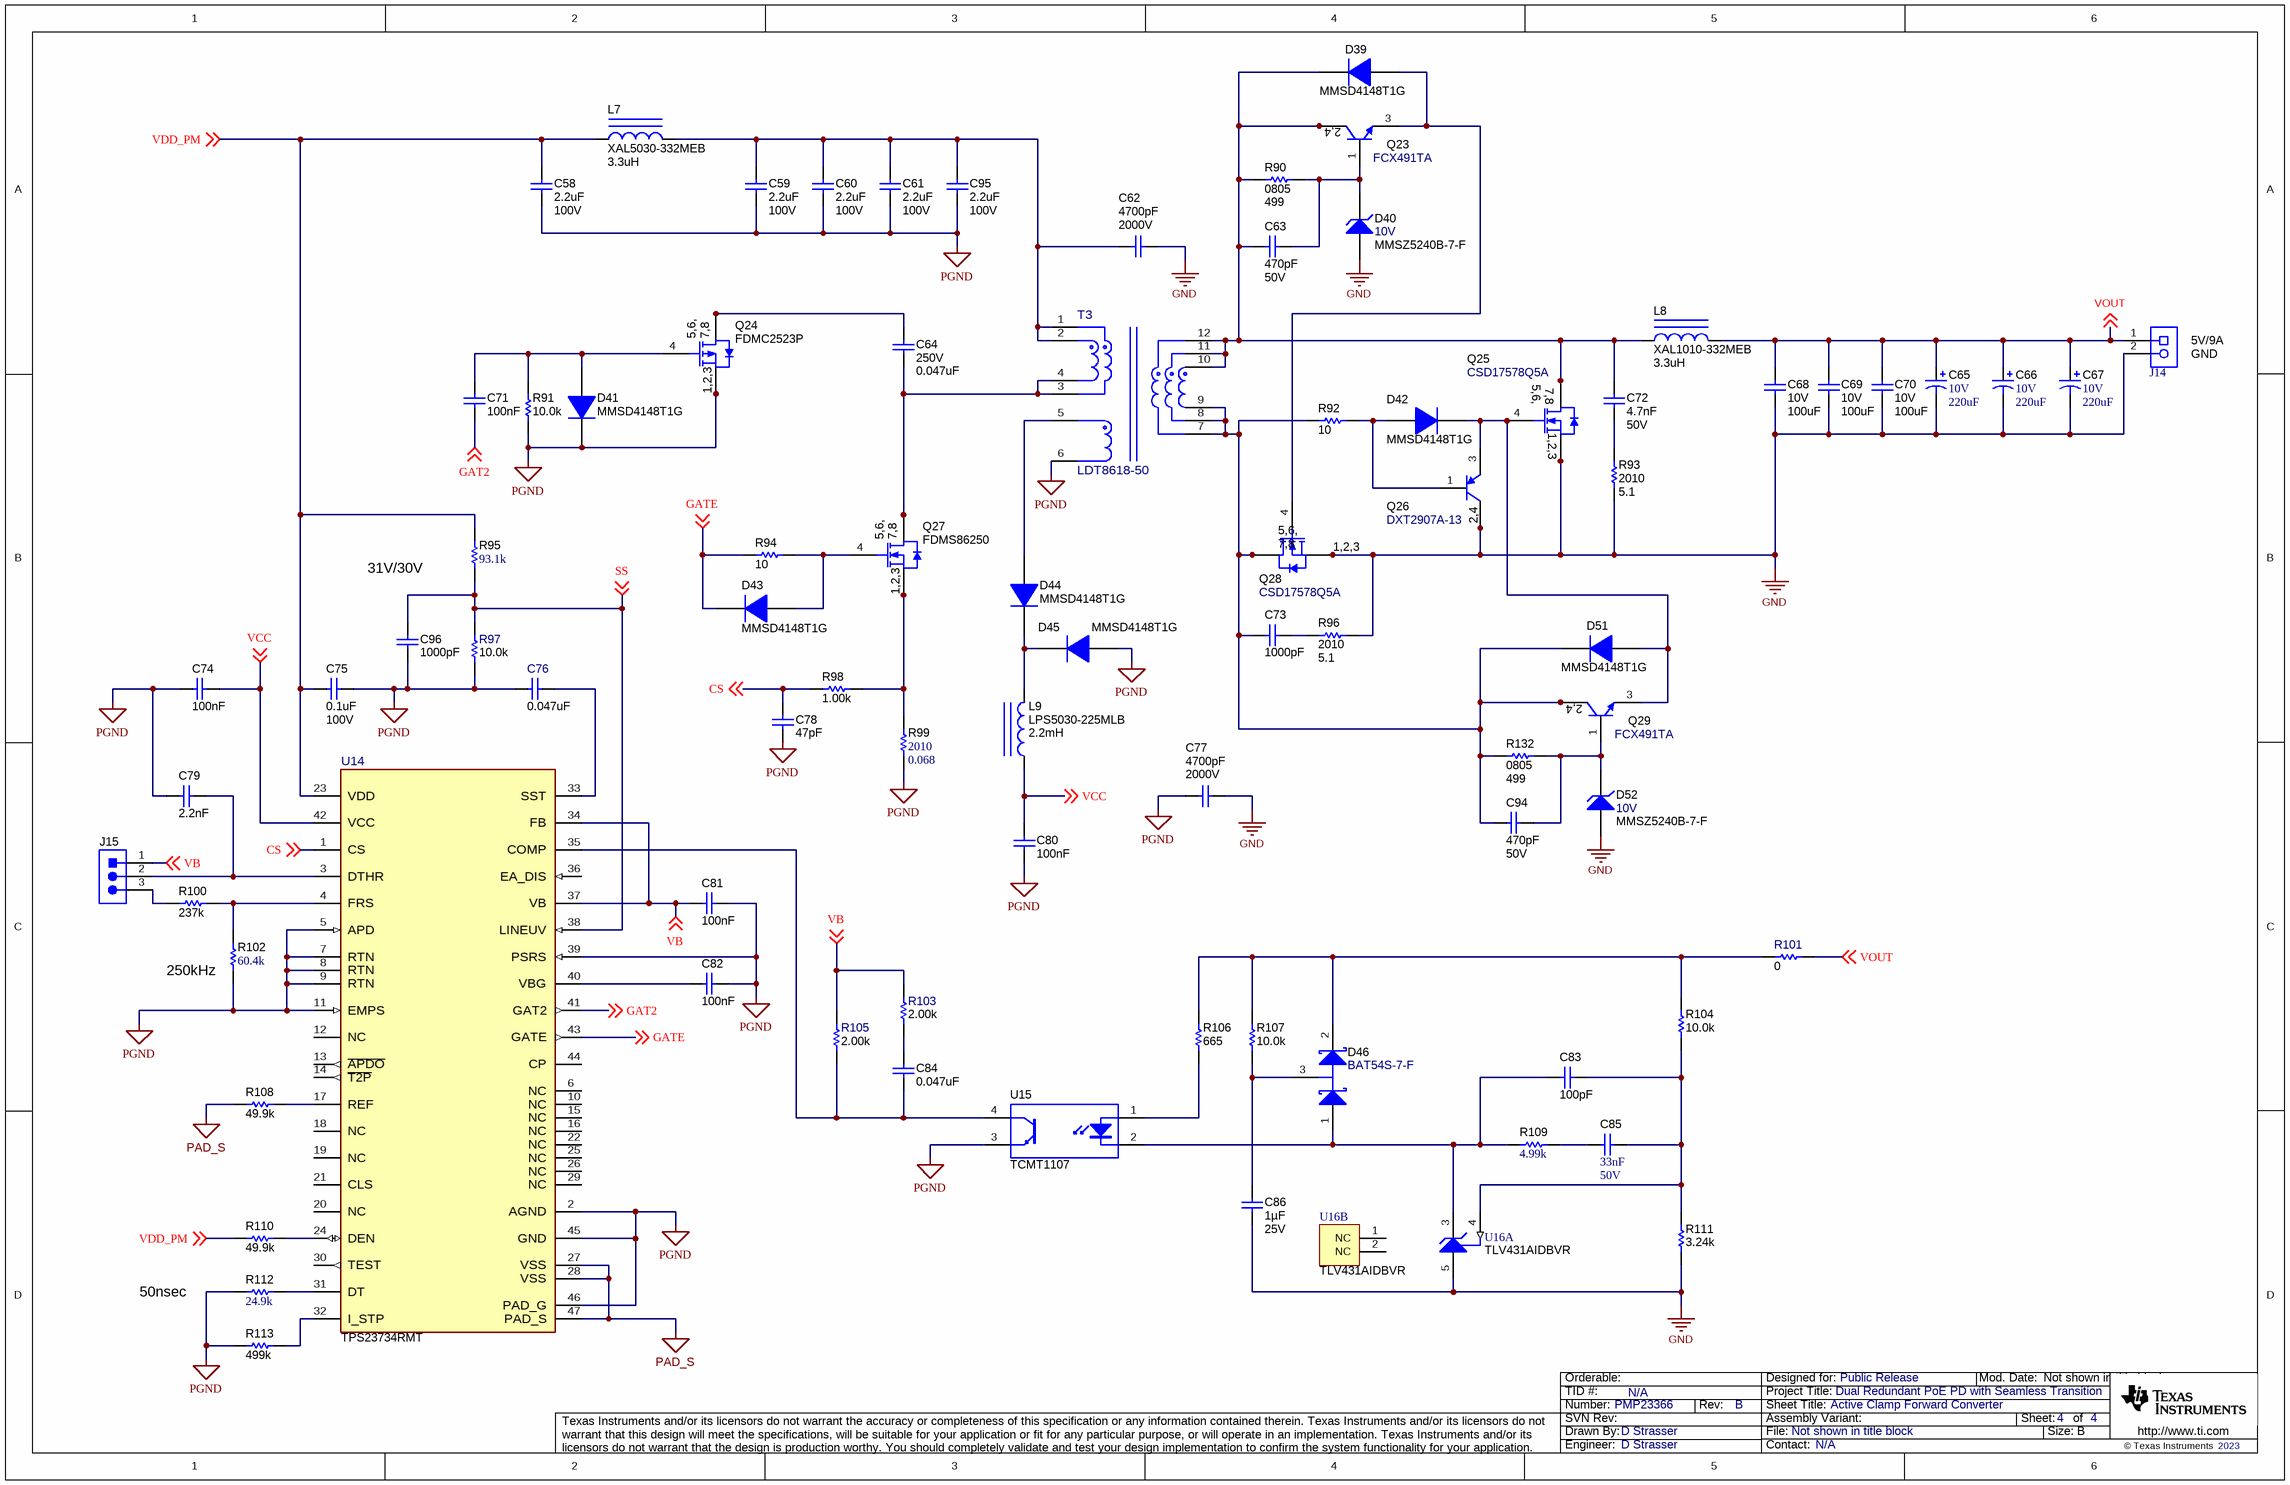
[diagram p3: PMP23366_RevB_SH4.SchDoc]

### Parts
C58  ValueDisplayed: 2.2uF  VDC_V: 100V  [1210_270]  (hidden comment: Capacitor)
C59  ValueDisplayed: 2.2uF  VDC_V: 100V  [1210_270]  (hidden comment: Capacitor)
C60  ValueDisplayed: 2.2uF  VDC_V: 100V  [1210_270]  (hidden comment: Capacitor)
C61  ValueDisplayed: 2.2uF  VDC_V: 100V  [1210_270]  (hidden comment: Capacitor)
C62  Value2: 2000V  ValueDisplayed: 4700pF  [1812_HV]  (hidden comment: Capacitor)
C63  Cap_F: 470pF  VDC_V: 50V  [0603L]  (hidden comment: 885012206081)
C64  VDC_V: 250V  ValueDisplayed: 0.047uF  [1206_180]  (hidden comment: GRM31CR72E473KW03L)
C65  VDC_V: 10V  ValueDisplayed: 220uF  [CAPSMT_62_F61]  (hidden comment: 10SVPE220M)
C66  VDC_V: 10V  ValueDisplayed: 220uF  [CAPSMT_62_F61]  (hidden comment: 10SVPE220M)
C67  VDC_V: 10V  ValueDisplayed: 220uF  [CAPSMT_62_F61]  (hidden comment: 10SVPE220M)
C68  VDC_V: 10V  ValueDisplayed: 100uF  [1210_280]  (hidden comment: C1210C107M8PACTU)
C69  VDC_V: 10V  ValueDisplayed: 100uF  [1210_280]  (hidden comment: C1210C107M8PACTU)
C70  VDC_V: 10V  ValueDisplayed: 100uF  [1210_280]  (hidden comment: C1210C107M8PACTU)
C71  Cap_F: 100nF  [0603L]  (hidden comment: 885012206095)
C72  Cap_F: 4.7nF  VDC_V: 50V  [0603]  (hidden comment: 885012206087)
C73  ValueDisplayed: 1000pF  [0603]  (hidden comment: Capacitor)
C74  Cap_F: 100nF  [0603L]  (hidden comment: 885012206095)
C75  ValueDisplayed: 0.1uF  Value2: 100V  [0805_HV1]  (hidden comment: Capacitor)
C76  ValueDisplayed: 0.047uF  [0603L]  (hidden comment: Capacitor)
C77  Value2: 2000V  ValueDisplayed: 4700pF  [1812_HV]  (hidden comment: Capacitor)
C78  ValueDisplayed: 47pF  [0603L]  (hidden comment: GRM1885C1H470JA01D)
C79  Cap_F: 2.2nF  [0603L]  (hidden comment: C0603C222K5RAC)
C80  Cap_F: 100nF  [0603L]  (hidden comment: 885012206095)
C81  Cap_F: 100nF  [0603L]  (hidden comment: 885012206095)
C82  Cap_F: 100nF  [0603L]  (hidden comment: 885012206095)
C83  ValueDisplayed: 100pF  [0603L]  (hidden comment: 885012006057)
C84  ValueDisplayed: 0.047uF  [0603L]  (hidden comment: Capacitor)
C85  Cap_F: 33nF  VDC_V: 50V  [0603L]  (hidden comment: GRM188R71H333KA61D)
C86  Cap_F: 1µF  VDC_V: 25V  [0805L]  (hidden comment: TMK212B7105KG-T)
C94  Cap_F: 470pF  VDC_V: 50V  [0603L]  (hidden comment: 885012206081)
C95  ValueDisplayed: 2.2uF  VDC_V: 100V  [1210_270]  (hidden comment: Capacitor)
C96  ValueDisplayed: 1000pF  [0603L]  (hidden comment: Capacitor)
D39  PartNumber: MMSD4148T1G  [SOD-123]  (hidden comment: DIODE)
D40  value 10V  PartNumber: MMSZ5240B-7-F  [SOD-123]  (hidden comment: Zener)
D41  PartNumber: MMSD4148T1G  [SOD-123]  (hidden comment: DIODE)
D42  PartNumber: MMSD4148T1G  [SOD-123]  (hidden comment: DIODE)
D43  PartNumber: MMSD4148T1G  [SOD-123]  (hidden comment: DIODE)
D44  PartNumber: MMSD4148T1G  [SOD-123]  (hidden comment: DIODE)
D45  PartNumber: MMSD4148T1G  [SOD-123]  (hidden comment: DIODE)
D46  BAT54S-7-F  [SOT-23L]
D51  PartNumber: MMSD4148T1G  [SOD-123]  (hidden comment: DIODE)
D52  value 10V  PartNumber: MMSZ5240B-7-F  [SOD-123]  (hidden comment: Zener)
J14  Receptacle_2x1  [On-Shore_ED120_2DS]  (value not drawn)
J15  TSW-103-07-G-S  [TSW-103-07-G-S]  (value not drawn)
L7  PartNumber: XAL5030-332MEB  ValueDisplayed: 3.3uH  [XAL5030]  (hidden comment: Inductor_Iron)
L8  ValueDisplayed: 3.3uH  [XAL1010]  (hidden comment: XAL1010-332MEB)
L9  PartNumber: LPS5030-225MLB  ValueDisplayed: 2.2mH  [LPS5030]  (hidden comment: Inductor_Iron)
Q23  FCX491TA  [SOT-89-3]
Q24  PartNumber: FDMC2523P  [MLP08S]  (hidden comment: MOSFET_P_D5678G4S123)
Q25  CSD17578Q5A  [DQJ0008A]
Q26  DXT2907A-13  [SOT-89-3]
Q27  FDMS86250  [TRANS_Fairchild_PQFN08A]
Q28  CSD17578Q5A  [DQJ0008A]
Q29  FCX491TA  [SOT-89-3]
R90  PackageReference: 0805  ValueDisplayed: 499  [0805_HV1]  (hidden comment: CRCW0805499RFKEA)
R91  value 10.0k  [0603L]  (hidden comment: Resistor)
R92  value 10  [0603L]  (hidden comment: Resistor)
R93  ValueDisplayed: 5.1  [2010]  (hidden comment: CRCW20105R10JNEF)
R94  ValueDisplayed: 10  [0603L]  (hidden comment: CRCW060310R0JNEA)
R95  ValueDisplayed: 93.1k  [0603L]  (hidden comment: CRCW060393K1FKEA)
R96  ValueDisplayed: 5.1  [2010]  (hidden comment: CRCW20105R10JNEF)
R97  ValueDisplayed: 10.0k  [0603L]  (hidden comment: Resistor)
R98  value 1.00k  [0603L]  (hidden comment: Resistor)
R99  ValueDisplayed: 0.068  [2010]  (hidden comment: MCR50JZHFSR068)
R100  ValueDisplayed: 237k  [0603L]  (hidden comment: CRCW0603237KFKEA)
R101  ValueDisplayed: 0  [0603L]  (hidden comment: Resistor)
R102  ValueDisplayed: 60.4k  [0603L]  (hidden comment: CRCW060360K4FKEA)
R103  ValueDisplayed: 2.00k  [0603L]  (hidden comment: Resistor)
R104  value 10.0k  [0603L]  (hidden comment: Resistor)
R105  ValueDisplayed: 2.00k  [0603L]  (hidden comment: Resistor)
R106  value 665  [0603L]  (hidden comment: Resistor)
R107  value 10.0k  [0603L]  (hidden comment: Resistor)
R108  ValueDisplayed: 49.9k  [0603L]  (hidden comment: CRCW060349K9FKEA)
R109  ValueDisplayed: 4.99k  [0603L]  (hidden comment: CRCW06034K99FKEA)
R110  ValueDisplayed: 49.9k  [0603L]  (hidden comment: CRCW060349K9FKEA)
R111  value 3.24k  [0603L]  (hidden comment: Resistor)
R112  ValueDisplayed: 24.9k  [0603L]  (hidden comment: CRCW060324K9FKEA)
R113  ValueDisplayed: 499k  [0603L]  (hidden comment: CRCW0603499KFKEA)
R132  PackageReference: 0805  ValueDisplayed: 499  [0805_HV1]  (hidden comment: CRCW0805499RFKEA)
T3  LDT8618-50  [FP-LDT8618-50_SMT_XFRFMR_21MM5_21MM1-MFG]
U14  TPS23734RMT  [RMT0045A-MFG]
U15  TCMT1107  [SOP-4]
U16  TLV431AIDBVR  [DBV0005A_L]  (parts A,B of 2)

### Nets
GND: C62.2 C65.2(-) C66.2(-) C67.2(-) C68.1 C69.1 C70.1 C77.2 C86.1 D40.2(A) D52.2(A) J14.2 Q25.1(S) Q25.2(S) Q25.3(S) Q26.2(C) Q26.4(C) Q28.1(S) Q28.2(S) Q28.3(S) R93.2 R96.2 R111.1 U16.5(ANODE)
PAD_S: R108.1 U14.27(VSS) U14.28(VSS) U14.47(PAD_S)
PGND: C58.2 C59.2 C60.2 C61.2 C74.1 C75.2 C76.2 C77.1 C78.1 C79.2 C80.1 C81.1 C82.1 C95.2 C96.2 D41.1(K) D45.2(A) Q24.1(S) Q24.2(S) Q24.3(S) R91.1 R97.1 R99.2 R102.2 R112.1 R113.1 T3.6 U14.2(AGND) U14.5(APD) U14.7(RTN) U14.8(RTN) U14.9(RTN) U14.11(EMPS) U14.39(PSRS) U14.45(GND) U14.46(PAD_G) U15.3(E)
CS: C78.2 R98.1 U14.1(CS) ; off-sheet CS
GAT2: C71.1 U14.41(GAT2) ; off-sheet GAT2
GATE: D43.1(K) R94.1 U14.43(GATE) ; off-sheet GATE
SS: C96.1 R95.2 R97.2 U14.38(LINEUV) ; off-sheet SS
VB: C81.2 J15.1 R103.2 R105.2 U14.34(FB) U14.37(VB) ; off-sheet VB
VCC: C74.2 C80.2 L9.1 U14.42(VCC) ; off-sheet VCC
VDD_PM: C58.1 C75.1 L7.1 R95.1 R110.1 U14.23(VDD) ; off-sheet VDD_PM
VOUT: C65.1(+) C66.1(+) C67.1(+) C68.2 C69.2 C70.2 J14.1 L8.2 R101.1 ; off-sheet VOUT
NetC59_1: C59.1 C60.1 C61.1 C62.1 C95.1 L7.2 T3.1 T3.2
NetC63_1: C63.1 D40.1(K) Q23.1(B) R90.2
NetC63_2: C63.2 C72.2 D39.1(K) L8.1 Q23.2(C) Q23.4(C) Q25.5(D) Q25.6(D) Q25.7(D) Q25.8(D) Q25.9(D) R90.1 T3.10 T3.11 T3.12
NetC64_1: C64.1 Q24.5(D) Q24.6(D) Q24.7(D) Q24.8(D)
NetC64_2: C64.2 Q27.5(D) Q27.6(D) Q27.7(D) Q27.8(D) T3.3 T3.4
NetC71_2: C71.2 D41.2(A) Q24.4(G) R91.2
NetC72_1: C72.1 R93.1
NetC73_1: C73.1 C94.2 D51.1(K) Q28.5(D) Q28.6(D) Q28.7(D) Q28.8(D) Q28.9(D) Q29.2(C) Q29.4(C) R92.2 R132.1 T3.7 T3.8 T3.9
NetC73_2: C73.2 R96.1
NetC76_1: C76.1 U14.33(SST)
NetC79_1: C79.1 J15.2 U14.3(DTHR)
NetC82_2: C82.2 U14.40(VBG)
NetC83_1: C83.1 C85.1 R104.2 R111.2 U16.4(REF)
NetC83_2: C83.2 D46.1(A) R109.1 U15.2(K) U16.3(CATHODE)
NetC84_1: C84.1 R103.1
NetC84_2: C84.2 R105.1 U14.35(COMP) U15.4(C)
NetC85_2: C85.2 R109.2
NetC86_2: C86.2 D46.3(C) R107.2
NetC94_1: C94.1 D52.1(K) Q29.1(B) R132.2
NetD39_2: D39.2(A) Q23.3(E) Q28.4(G)
NetD42_1: D42.1(K) D51.2(A) Q25.4(G) Q26.3(E) Q29.3(E)
NetD42_2: D42.2(A) Q26.1(B) R92.1
NetD43_2: D43.2(A) Q27.4(G) R94.2
NetD44_1: D44.1(K) D45.1(K) L9.2
NetD44_2: D44.2(A) T3.5
NetD46_2: D46.2(K) R101.2 R104.1 R106.2 R107.1
NetJ15_3: J15.3 R100.1
NetQ27_1: Q27.1(S) Q27.2(S) Q27.3(S) R98.2 R99.1
NetR100_2: R100.2 R102.1 U14.4(FRS)
NetR106_1: R106.1 U15.1(A)
NetR108_2: R108.2 U14.17(REF)
NetR110_2: R110.2 U14.24(DEN)
NetR112_2: R112.2 U14.31(DT)
NetR113_2: R113.2 U14.32(I_STP)

Not connected (* = marked no-connect by the designer): U14 6(NC) 10(NC) 12(NC) 13(~{APDO}) 14(~{T2P}) 15(NC) 16(NC) 18(NC) 19(NC) 20(NC) 21(CLS) 22(NC) 25(NC) 26(NC) 29(NC) 30(TEST) 36(EA_DIS) 44(CP); U16 1(NC) 2(NC)

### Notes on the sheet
- (near J14) 5V/9A
- (near J14) GND
- 31V/30V
- (near R102) 250kHz
- 50nsec

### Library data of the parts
C58-C61 C95 = CMP-0009232-2: CAP, CERM, 2.2 uF, 100 V, +/- 10%, X7R, 1210; PartNumber: GRM32ER72A225KA35L; Manufacturer: MuRata; Polarized: N; Value: 2.2uF; U/M: EA; Cap_F: 2.2µF; ESR_ohm: 7m; Value1: 0.007 ohm; IRMS_A: 4.4A; TaMin_C: -55°C; TaMax_C: 125°C; Cap_Case: 1210; AEC Category: Q200; SizeArea_mm2: 8; SizeAreaWB_mm2: 14.7; SizeX_mm: 3.2; SizeY_mm: 2.5; SizeZ_mm: 2.7
C62 C77 = CMP-0009294-2: CAP, CERM, 4700 pF, 2000 V, +/- 10%, X7R, 1812; Manufacturer: AVX; PartNumber: 1812GC472KA1; Value: 4700pF; Polarized: N; U/M: EA; Cap_F: 4.7nF; Value1: Unknown; VDC_V: 2kV; TaMin_C: -55°C; TaMax_C: 125°C; Cap_Case: 1812; AEC Category: Q200; SizeArea_mm2: 14.4; SizeAreaWB_mm2: 23.1; SizeX_mm: 4.5; SizeY_mm: 3.2; SizeZ_mm: 1.35
C63 C94 = CMP-0006834-5: CAP, CERM, 470 pF, 50 V, +/- 10%, X7R, 0603; Manufacturer: Wurth Elektronik; TaMin_C: -55°C; Polarized: N; SizeAreaWB_mm2: 4.68; Value1: Unknown; U/M: EA; Value: 470pF; TaMax_C: 125°C; SizeZ_mm: 1; SizeX_mm: 1.6; SizeY_mm: 0.8; Cap_Case: 0603; SizeArea_mm2: 1.28; AEC Category: Q200
C64 = CMP-0008975-2: CAP, CERM, 0.047 uF, 250 V, +/- 10%, X7R, 1206; Manufacturer: MuRata; TaMin_C: -55°C; Polarized: N; SizeAreaWB_mm2: 10.92; Value1: Unknown; U/M: EA; TaMax_C: 125°C; SizeZ_mm: 1.8; SizeX_mm: 3.2; SizeY_mm: 1.6; Cap_Case: 1206; SizeArea_mm2: 5.12; Cap_F: 47nF; AEC Category: Q200
C65-C67 = CMP-0012073-3: CAP, Aluminum Polymer, 220 uF, 10 V, +/- 20%, 0.02 ohm, F61 SMD; Manufacturer: Panasonic; TaMin_C: -55°C; ESR_ohm: 20m; Polarized: Y; SizeAreaWB_mm2: 73.96; Value: 220uF; TaMax_C: 105°C; SizeZ_mm: 5.8; SizeX_mm: 6.6; SizeArea_mm2: 43.56; CompType: Capacitor; Cap_F: 220µF; IRMS_A: 2.7A; AEC Category: Q200
C68-C70 = CMP-0009082-2: CAP, CERM, 100 uF, 10 V, +/- 20%, X5R, 1210; Manufacturer: Wurth Elektronik; TaMin_C: -55°C; Polarized: N; SizeAreaWB_mm2: 14.7; Value1: Unknown; U/M: EA; Value: 100uF; TaMax_C: 85°C; SizeZ_mm: 2.8; SizeX_mm: 3.2; SizeY_mm: 2.5; Cap_Case: 1210; SizeArea_mm2: 8; Cap_F: 100µF; AEC Category: Q200
C71 C74 C80-C82 = CMP-0006837-4: CAP, CERM, 0.1 uF, 50 V, +/- 10%, X7R, 0603; Manufacturer: Wurth Elektronik; TaMin_C: -55°C; Polarized: N; SizeAreaWB_mm2: 4.68; Value1: Unknown; U/M: EA; Value: 0.1uF; TaMax_C: 125°C; SizeZ_mm: 1; SizeX_mm: 1.6; SizeY_mm: 0.8; Cap_Case: 0603; Value2: 50V; SizeArea_mm2: 1.28; AEC Category: Q200
C72 = CMP-0006835-4: CAP, CERM, 4700 pF, 50 V, +/- 10%, X7R, 0603; Manufacturer: Wurth Elektronik; TaMin_C: -55°C; Polarized: N; SizeAreaWB_mm2: 4.68; Value1: Unknown; U/M: EA; Value: 4700pF; TaMax_C: 125°C; SizeZ_mm: 1; SizeX_mm: 1.6; SizeY_mm: 0.8; SizeArea_mm2: 1.28; AEC Category: Q200
C73 = CMP-0007432-5: CAP, CERM, 1000 pF, 50 V, +/- 10%, X7R, 0603; PartNumber: GRM188R71H102KA01D; Manufacturer: MuRata; Polarized: N; Value: 1000pF; U/M: EA; Cap_F: 1nF; Value1: Unknown; VDC_V: 50V; TaMin_C: -55°C; TaMax_C: 125°C; SizeArea_mm2: 1.28; SizeAreaWB_mm2: 4.68; SizeX_mm: 1.6; SizeY_mm: 0.8; SizeZ_mm: 1; AEC Category: Q200
C75 = CMP-0007886-2: as C57 on sheet PMP23366_RevB_SH3
C76 = CMP-0007049-4: CAP, CERM, 0.047 uF, 50 V, +/- 10%, X7R, 0603; PartNumber: C1608X7R1H473K080AA; Manufacturer: TDK; Polarized: N; U/M: EA; Cap_F: 47nF; ESR_ohm: 0.049007; Value1: 0.049007 ohm; VDC_V: 50V; IRMS_A: 7.67528dA; TaMin_C: -55°C; TaMax_C: 125°C; Cap_Case: 0603; AEC Category: Q200; SizeArea_mm2: 1.28; SizeAreaWB_mm2: 4.68; SizeX_mm: 1.6; SizeY_mm: 0.8; SizeZ_mm: 1
C78 = CMP-0007220-4: CAP, CERM, 47 pF, 50 V, +/- 5%, C0G/NP0, 0603; Manufacturer: MuRata; TaMin_C: -55°C; Polarized: N; SizeAreaWB_mm2: 4.68; Value1: Unknown; U/M: EA; Value: 47pF; TaMax_C: 125°C; SizeZ_mm: 1; SizeX_mm: 1.6; SizeY_mm: 0.8; Cap_Case: 0603; Value2: 50V; SizeArea_mm2: 1.28; AEC Category: Q200
C79 = CMP-0006897-4: CAP, CERM, 2200 pF, 50 V, +/- 10%, X7R, 0603; Manufacturer: Kemet; TaMin_C: -55°C; Polarized: N; SizeAreaWB_mm2: 4.68; Value1: Unknown; U/M: EA; Value: 2200pF; TaMax_C: 125°C; SizeZ_mm: 1; SizeX_mm: 1.6; SizeY_mm: 0.8; Cap_Case: 0603; Value2: 50V; SizeArea_mm2: 1.28; AEC Category: Q200
C83 = CMP-0006822-4: as C92 on sheet PMP23366_RevB_SH3
C84 = CMP-0007049-4: CAP, CERM, 0.047 uF, 50 V, +/- 10%, X7R, 0603; PartNumber: C1608X7R1H473K080AA; Manufacturer: TDK; Polarized: N; U/M: EA; Cap_F: 47nF; ESR_ohm: 0.049007; Value1: 0.049007 ohm; VDC_V: 50V; IRMS_A: 7.67528dA; TaMin_C: -55°C; TaMax_C: 125°C; Cap_Case: 0603; SizeArea_mm2: 1.28; SizeAreaWB_mm2: 4.68; SizeX_mm: 1.6; SizeY_mm: 0.8; SizeZ_mm: 1; AEC Category: Q200
C85 = CMP-0007451-4: CAP, CERM, 0.033 uF, 50 V, +/- 10%, X7R, 0603; Manufacturer: MuRata; TaMin_C: -55°C; Polarized: N; SizeAreaWB_mm2: 4.68; Value1: Unknown; U/M: EA; TaMax_C: 125°C; SizeZ_mm: 1; SizeX_mm: 1.6; SizeY_mm: 0.8; Cap_Case: 0603; SizeArea_mm2: 1.28; AEC Category: Q200
C86 = CMP-0008412-2: as C50 on sheet PMP23366_RevB_SH3
C96 = CMP-0007432-5: as C56 on sheet PMP23366_RevB_SH3
D39 D41-D45 D51 = CMP-0029032-2: Diode, Switching, 100 V, 0.2 A, SOD-123; Manufacturer: ON Semiconductor; Value: 100V; Vf_V: 1V; Io_A: 200mA; Value1: 0.2A; TJmax_C: 150°C; AEC Category: Q101; Green_Lifecycle: Active; Green_REACh: Passed; SizeArea_mm2: 6.545; SizeAreaWB_mm2: 13.095; SizeX_mm: 3.85; SizeY_mm: 1.7; SizeZ_mm: 1.35
D40 D52 = CMP-0005749-3: Diode, Zener, 10 V, 500 mW, SOD-123; Manufacturer: Diodes Inc.; Power_W: 500mW; Value1: 0.5W; RJA_CperW: 350; AEC Category: Q101; SizeArea_mm2: 6.545; SizeAreaWB_mm2: 13.095; SizeX_mm: 3.85; SizeY_mm: 1.7; SizeZ_mm: 1.35
D46 = CMP-0028456-2: Diode, Schottky, 30 V, 0.2 A, SOT-23; Manufacturer: Diodes Inc.; Vf_V: 650mV; SizeAreaWB_mm2: 14; SizeX_mm: 2.5; TJmax_C: 125°C; SizeZ_mm: 1.1; Value2: 0.65V; SizeArea_mm2: 7.5; SizeY_mm: 3; Vr_V: 30V; AEC Category: Q101; Io_A: 200mA; Value1: 0.2A; Green_Lifecycle: Active; Value: 30V; Green_REACh: Passed
J14 = CMP-0074910-1: Terminal Block, 5.08 mm, 2x1, Brass, TH; PartNumber: ED120/2DS; Manufacturer: On-Shore Technology; Cert_CULUS: Y; CNHeader: False; CT: True; Current_A: 15A; Gender: Female; Green_Lifecycle: Not Set; Green_REACh: Incomplete; Pitch_mm: 5.08; Row_Count: 1; Shrouded: N; Voltage_V: 300V
J15 = CMP-0075407-2: Header, 100mil, 3x1, Gold, TH; Manufacturer: Samtec; Pitch_mm: 2.54; Cert_VDE: N; Gender: Male; Cert_CSA: Y; Voltage_V: 550V; Green_REACh: Passed; Current_A: 6.3A; Green_Lifecycle: Active; Row_Count: 1
L7 = CMP-0061003-2: Inductor, Shielded, Composite, 3.3 µH, 8.1 A, 0.02 ohm, AEC-Q200 Grade 1, SMD; Manufacturer: Coilcraft; Value: 3.3uH; Ind_H: 3.3µH; Imax_A: 8.1A; Irms: 8.1A @ 40C rise; Isat: 8.7A @ 30% inductance drop; DCR_ohm: 0.02; AEC Category: Q200; AEC Grade: Y; AEC Qualified: 1; Green_Lifecycle: Not Set; Green_REACh: Incomplete; SizeArea_mm2: 28.9344; SizeAreaWB_mm2: 54.4544; SizeX_mm: 5.28; SizeY_mm: 5.48; SizeZ_mm: 3.1
L8 = CMP-0060948-1: Inductor, Shielded, Composite, 3.3 uH, 25 A, 0.0037 ohm, SMD; Manufacturer: Coilcraft; Isat: 27.4A @ 30% inductance drop; Irms: 25A @ 40C rise; Green_Lifecycle: Not Set; SizeAreaWB_mm2: 159.6; DCR_ohm: 3.7m; Green_REACh: Incomplete; Value: 3.3uH; Imax_A: 25A; SizeZ_mm: 10; SizeX_mm: 11.3; SizeArea_mm2: 113; Ind_H: 3.3µH; AEC Category: Q200
L9 = CMP-0062000-2: Inductor, Shielded Drum Core, Ferrite, 2.2 mH, 0.08 A, 11 ohm, SMD; Manufacturer: Coilcraft; Value: 2.2mH; Imax_A: 80mA; Irms: 0.15A @ 40C rise; Isat: 0.08A @ 30% inductance drop; DCR_ohm: 11; Value1: 11 ohm; Value2: 0.08A; AEC Category: Q200; Green_Lifecycle: Not Set; Green_REACh: Incomplete; SizeArea_mm2: 23.04; SizeAreaWB_mm2: 33.64; SizeX_mm: 4.8; SizeZ_mm: 2.9
Q23 Q29 = CMP-0000483-2: Transistor, NPN, 60 V, 1 A, AEC-Q101, SOT-89; Manufacturer: Diodes Inc.; TaMax_C: 150°C; Value2: 300; Value1: 1 A; Vcesat1_V: 100mV; SizeX_mm: 4.1; SizeY_mm: 4.5; TaMin_C: -65°C; IcRated_A: 1A; CompType: BJT; SizeZ_mm: 1.5; AEC Qualified: Y; Value: 60 V; SizeArea_mm2: 18.45; NPN: 1; Vceo_V: 60V; PNP: 0; AEC Category: Q101; SizeAreaWB_mm2: 28.05; U/M: EA
Q24 = CMP-0000056-3: MOSFET, P-CH, -150 V, -3 A, QFN-8; Manufacturer: Fairchild Semiconductor; Alternate Manufacturer: None; Value: -150V; ChType: P; Value2: 6.2 nC; QgTyp_nC: 6.2; Vgs_V: -30V; IdsMax_A: -3A; AEC Category: Q101; AEC Qualified: N; ChMode: Enhancement; SizeArea_mm2: 10.89; SizeAreaWB_mm2: 18.49; SizeX_mm: 3.3; SizeZ_mm: 0.8
Q25 Q28 = CMP-0000592-1: MOSFET, N-CH, 30 V, 25 A, DQJ0008A (VSONP-8); Alternate Manufacturer: None; Manufacturer: Texas Instruments; SizeZ_mm: 1.1; ChType: N; Value2: 17.2 nC; Value1: 0.009; VdsMax_V: 30V; SizeX_mm: 6; SizeAreaWB_mm2: 55.2; SizeY_mm: 4.9; Vgs_V: 20V; QgTyp_nC: 17.2; Value: 30V; Rdson45_ohm: 9.3m; SizeArea_mm2: 29.4; AEC Category: Q101; IdsMax_A: 25A; U/M: EA
Q26 = CMP-0000356-2: Transistor, PNP, 60 V, 0.6 A, AEC-Q101, SOT-89; Manufacturer: Diodes Inc.; TaMax_C: 150°C; Value2: 300; Value1: 0.6 A; Vcesat1_V: 130mV; SizeX_mm: 4.1; SizeY_mm: 4.5; TaMin_C: -55°C; IcRated_A: 600mA; CompType: BJT; SizeZ_mm: 1.5; AEC Qualified: Y; Value: 60 V; SizeArea_mm2: 18.45; NPN: 0; Vceo_V: 60V; PNP: 1; AEC Category: Q101; SizeAreaWB_mm2: 28.05; U/M: EA
Q27 = CMP-0001057-1: MOSFET, N-CH, 150 V, 6.7 A, PQFN08A; Alternate Manufacturer: None; Manufacturer: Fairchild Semiconductor; SizeZ_mm: 1.1; ChType: N; Value2: 36 nC; Value1: 0.02; VdsMax_V: 150V; SizeX_mm: 5; SizeY_mm: 6; Vgs_V: 4V; Value: 150V; Rdson45_ohm: 25m; SizeArea_mm2: 30; AEC Category: Q101; IdsMax_A: 6.7A; SizeAreaWB_mm2: 56; U/M: EA; QgTyp_nC: 36
R90 R132 = CMP-0021282-3: RES, 499, 1%, 0.125 W, AEC-Q200 Grade 0, 0805; Manufacturer: Vishay-Dale; Power_W: 125mW; TempCo: 100 ppm/C; Value_Code: 499R; Value: 499; EIA_Code: E96; SizeX_mm: 2; SizeY_mm: 1.25; SizeZ_mm: 1.45; Value2: 0.125W; SizeArea_mm2: 2.5; AEC Qualified: Y; VDC_V: 150V; AEC Category: Q200; AEC Grade: 0
R91 R104 R107 = CMP-0021998-4: RES, 10.0 k, 1%, 0.1 W, AEC-Q200 Grade 0, 0603; PartNumber: CRCW060310K0FKEA; Manufacturer: Vishay-Dale; Res_ohm: 10k; Value_Code: 10k0; Power_W: 100mW; Value2: 0.1W; VDC_V: 75V; TempCo: 100 ppm/C; EIA_Code: E96; AEC Category: Q200; AEC Grade: 0; AEC Qualified: Y; SizeArea_mm2: 1.28; SizeX_mm: 1.6; SizeY_mm: 0.8; SizeZ_mm: 1
R92 = CMP-0025703-4: RES, 10, 5%, 0.1 W, AEC-Q200 Grade 0, 0603; PartNumber: CRCW060310R0JNEA; Manufacturer: Vishay-Dale; Value_Code: 10R0; Power_W: 100mW; Value2: 0.1W; VDC_V: 75V; TempCo: 200 ppm/C; EIA_Code: E24; AEC Category: Q200; AEC Grade: 0; AEC Qualified: Y; SizeArea_mm2: 1.28; SizeX_mm: 1.6; SizeY_mm: 0.8; SizeZ_mm: 1
R93 R96 = CMP-0016161-3: RES, 5.1, 5%, 0.75 W, AEC-Q200 Grade 0, 2010; Manufacturer: Vishay-Dale; Power_W: 750mW; TempCo: 200 ppm/C; Value_Code: 5R10; Value: 5.1; EIA_Code: E24; SizeX_mm: 5; SizeY_mm: 2.5; SizeZ_mm: 1.66; Value2: 0.75W; SizeArea_mm2: 12.5; AEC Qualified: Y; VDC_V: 400V; AEC Grade: 0; AEC Category: Q200
R94 = CMP-0025703-4: RES, 10, 5%, 0.1 W, AEC-Q200 Grade 0, 0603; Manufacturer: Vishay-Dale; Power_W: 100mW; TempCo: 200 ppm/C; Value_Code: 10R0; Value: 10; EIA_Code: E24; SizeX_mm: 1.6; SizeY_mm: 0.8; SizeZ_mm: 1; Value2: 0.1W; SizeArea_mm2: 1.28; AEC Qualified: Y; VDC_V: 75V; AEC Category: Q200; AEC Grade: 0
R95 = CMP-0022655-4: RES, 93.1 k, 1%, 0.1 W, AEC-Q200 Grade 0, 0603; Manufacturer: Vishay-Dale; Power_W: 100mW; TempCo: 100 ppm/C; Value_Code: 93k1; Value: 93.1k; EIA_Code: E96; SizeX_mm: 1.6; SizeY_mm: 0.8; SizeZ_mm: 1; Value2: 0.1W; SizeArea_mm2: 1.28; AEC Qualified: Y; VDC_V: 75V; AEC Category: Q200; AEC Grade: 0
R97 = CMP-0021998-4: RES, 10.0 k, 1%, 0.1 W, AEC-Q200 Grade 0, 0603; PartNumber: CRCW060310K0FKEA; Manufacturer: Vishay-Dale; Value: 10.0k; Res_ohm: 10k; Value_Code: 10k0; Power_W: 100mW; Value2: 0.1W; VDC_V: 75V; TempCo: 100 ppm/C; EIA_Code: E96; AEC Category: Q200; AEC Qualified: Y; AEC Grade: 0; SizeArea_mm2: 1.28; SizeX_mm: 1.6; SizeY_mm: 0.8; SizeZ_mm: 1
R98 = CMP-0022109-5: as R76 on sheet PMP23366_RevB_SH3
R99 = CMP-0065760-2: RES, 0.068, 1%, .5 W, AEC-Q200 Grade 0, 2010; Manufacturer: Rohm; Power_W: 500mW; TempCo: 800 ppm/C; Value_Code: R068; U/M: EA; Value: 0.068; Res_ohm: 68m; SizeX_mm: 5.0; SizeY_mm: 2.5; SizeZ_mm: 1.66; Value2: .5W; SizeArea_mm2: 12.5; AEC Qualified: Y; AEC Grade: 0; AEC Category: Q200
R100 = CMP-0022226-4: RES, 237 k, 1%, 0.1 W, AEC-Q200 Grade 0, 0603; Manufacturer: Vishay-Dale; Power_W: 100mW; TempCo: 100 ppm/C; Value: 237k; EIA_Code: E96; SizeX_mm: 1.6; SizeY_mm: 0.8; SizeZ_mm: 1; Value2: 0.1W; SizeArea_mm2: 1.28; AEC Qualified: Y; VDC_V: 75V; AEC Category: Q200; AEC Grade: 0
R101 = CMP-0025697-4: RES, 0, 5%, 0.1 W, AEC-Q200 Grade 0, 0603; PartNumber: CRCW06030000Z0EA; Manufacturer: Vishay-Dale; Value: 0; Value_Code: 0000; Power_W: 100mW; Value2: 0.1W; VDC_V: 75V; TempCo: 200 ppm/C; EIA_Code: E24; AEC Category: Q200; AEC Qualified: Y; SizeArea_mm2: 1.28; SizeX_mm: 1.6; SizeY_mm: 0.8; SizeZ_mm: 1
R102 = CMP-0022532-4: RES, 60.4 k, 1%, 0.1 W, AEC-Q200 Grade 0, 0603; Manufacturer: Vishay-Dale; Power_W: 100mW; TempCo: 100 ppm/C; Value_Code: 60k4; Value: 60.4k; EIA_Code: E96; SizeX_mm: 1.6; SizeY_mm: 0.8; SizeZ_mm: 1; Value2: 0.1W; SizeArea_mm2: 1.28; AEC Qualified: Y; VDC_V: 75V; AEC Category: Q200; AEC Grade: 0
R103 R105 = CMP-0022268-4: RES, 2.00 k, 1%, 0.1 W, AEC-Q200 Grade 0, 0603; PartNumber: CRCW06032K00FKEA; Manufacturer: Vishay-Dale; Value: 2.00k; Res_ohm: 2k; Value_Code: 2k00; Power_W: 100mW; Value2: 0.1W; VDC_V: 75V; TempCo: 100 ppm/C; EIA_Code: E96; AEC Category: Q200; AEC Qualified: Y; AEC Grade: 0; SizeArea_mm2: 1.28; SizeX_mm: 1.6; SizeY_mm: 0.8; SizeZ_mm: 1
R106 = CMP-0022547-5: RES, 665, 1%, 0.1 W, AEC-Q200 Grade 0, 0603; PartNumber: CRCW0603665RFKEA; Manufacturer: Vishay-Dale; Value_Code: 665R; Power_W: 100mW; Value2: 0.1W; VDC_V: 75V; TempCo: 100 ppm/C; EIA_Code: E96; AEC Category: Q200; AEC Grade: 0; AEC Qualified: Y; SizeArea_mm2: 1.28; SizeX_mm: 1.6; SizeY_mm: 0.8; SizeZ_mm: 1
R108 R110 = CMP-0022447-4: RES, 49.9 k, 1%, 0.1 W, AEC-Q200 Grade 0, 0603; Manufacturer: Vishay-Dale; Power_W: 100mW; TempCo: 100 ppm/C; Value_Code: 49k9; Value: 49.9k; EIA_Code: E96; SizeX_mm: 1.6; SizeY_mm: 0.8; SizeZ_mm: 1; Value2: 0.1W; SizeArea_mm2: 1.28; AEC Qualified: Y; VDC_V: 75V; AEC Category: Q200; AEC Grade: 0
R109 = CMP-0022458-4: as R82 on sheet PMP23366_RevB_SH3
R111 = CMP-0022374-4: RES, 3.24 k, 1%, 0.1 W, AEC-Q200 Grade 0, 0603; PartNumber: CRCW06033K24FKEA; Manufacturer: Vishay-Dale; Value_Code: 3k24; Power_W: 100mW; Value2: 0.1W; VDC_V: 75V; TempCo: 100 ppm/C; EIA_Code: E96; AEC Category: Q200; AEC Grade: 0; AEC Qualified: Y; SizeArea_mm2: 1.28; SizeX_mm: 1.6; SizeY_mm: 0.8; SizeZ_mm: 1
R112 = CMP-0022237-4: RES, 24.9 k, 1%, 0.1 W, AEC-Q200 Grade 0, 0603; Manufacturer: Vishay-Dale; Power_W: 100mW; TempCo: 100 ppm/C; Value_Code: 24k9; Value: 24.9k; EIA_Code: E96; SizeX_mm: 1.6; SizeY_mm: 0.8; SizeZ_mm: 1; Value2: 0.1W; SizeArea_mm2: 1.28; AEC Qualified: Y; VDC_V: 75V; AEC Category: Q200; AEC Grade: 0
R113 = CMP-0022445-4: RES, 499 k, 1%, 0.1 W, AEC-Q200 Grade 0, 0603; Manufacturer: Vishay-Dale; Power_W: 100mW; TempCo: 100 ppm/C; Value: 499k; EIA_Code: E96; SizeX_mm: 1.6; SizeY_mm: 0.8; SizeZ_mm: 1; Value2: 0.1W; SizeArea_mm2: 1.28; AEC Qualified: Y; VDC_V: 75V; AEC Category: Q200; AEC Grade: 0
T3 = CMP-0087855-1: DC/DC Transformer; Manufacturer: LinkCom; Ind_H: 100µH; Ns1toNp: 1.71:1/4:1; AEC Qualified: No; SizeZ_mm: 12mm; DCR_ohm: 0.03
U14 = CMP-0089621-1: IEEE 802.3bt Type 3 Class 1-4 PoE PD with High Efficiency DC-DC Controller; Manufacturer: Texas Instruments; Number Of Outputs: 1; AEC Qualified: No; TJmax_C: +125°C; Switching Topology: Flyback,Other; Standoff Height: 0mm; SizeZ_mm: 1mm; Switching Frequency: 250kHz
U15 = CMP-0006166-3: Optocoupler, 3.75 kV, 80-160% CTR, SMT; Manufacturer: Vishay-Semiconductor; CTR (Max): 160%; SizeAreaWB_mm2: 43.65; CTR (Min): 80%; SizeZ_mm: 2.3; SizeX_mm: 7; SizeY_mm: 2.85; SizeArea_mm2: 19.95; Voltage_Isolation_Vrms: 3.75kV
U16 = CMP-0032952-1: Low Voltage Adjustable Precision Shunt Regulator, 39 ppm / degC, 15 mA, -40 to 85 degC, 5-pin SOT-23 (DBV), Green (RoHS & no Sb/Br); Manufacturer: Texas Instruments; Initial Accuracy @ 25/deg C(%): 1; Min Iz for Regulation(uA): 80; VO Adj(Min)(V): 1.24; VO Adj(Max)(V): 6; SubFamily: Shunt Voltage Reference; Temp Coeff(Max)(ppm/ degree C): 129; Temp Coeff(Typ)(ppm/ degree C): 39; Rating: Catalog; Iout/Iz(Max)(mA): 15

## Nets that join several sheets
GND: PMP23366_RevB_SH2 (9 pins), PMP23366_RevB_SH3 (8 pins), PMP23366_RevB_SH4 (24 pins)
PGND: PMP23366_RevB_SH2 (28 pins), PMP23366_RevB_SH3 (28 pins), PMP23366_RevB_SH4 (37 pins)
RTN1: PMP23366_RevB_SH2 (6 pins), PMP23366_RevB_SH3 (6 pins)
AUX: PMP23366_RevB_SH2 (5 pins), PMP23366_RevB_SH3 (R87.2)
AUX_OUT_1: PMP23366_RevB_SH2 (R37.2), PMP23366_RevB_SH3 (Q21.3)
AUX_OUT_2: PMP23366_RevB_SH2 (R62.2), PMP23366_RevB_SH3 (D47.2 D48.2)
PG1_EN: PMP23366_RevB_SH2 (D53.2), PMP23366_RevB_SH3 (Q31.1 R134.2 U20.1)
SS: PMP23366_RevB_SH2 (Q13.3), PMP23366_RevB_SH4 (C96.1 R95.2 R97.2 U14.38)
VCC: PMP23366_RevB_SH3 (C45.1 U8.2), PMP23366_RevB_SH4 (C74.2 C80.2 L9.1 U14.42)
VDD: PMP23366_RevB_SH1 (C2.1 C14.1 L1.2 L3.2), PMP23366_RevB_SH2 (38 pins), PMP23366_RevB_SH3 (10 pins)
VDD_PM: PMP23366_RevB_SH3 (R71.2 R73.1), PMP23366_RevB_SH4 (6 pins)
VOUT: PMP23366_RevB_SH2 (R53.2), PMP23366_RevB_SH3 (C47.1 R70.1 U9.2), PMP23366_RevB_SH4 (9 pins)
VSS_1: PMP23366_RevB_SH1 (C2.2 L2.2), PMP23366_RevB_SH2 (10 pins)
VSS_2: PMP23366_RevB_SH1 (C14.2 L4.2), PMP23366_RevB_SH2 (10 pins)

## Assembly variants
001: not fitted C29 C36 C43 C47 C48 C52 C53 C90 C91 C92 C93 C94 D5 D6 D7 D8 D13 D14 D15 D16 D51 D52 FID1 FID2 FID3 Q29 R117 R118 R119 R120 R121 R122 R123 R124 R125 R126 R127 R128 R129 R132 U9 U18 U19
